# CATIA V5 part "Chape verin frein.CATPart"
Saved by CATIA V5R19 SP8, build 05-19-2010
Part number: Chape verin frein
Bounding box of the stored display mesh (mm): x -155 to 155, y -1185 to -885, z -1549.899 to -1325
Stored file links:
  G:\EU_thinkMotion\CFAO_2010\MMS_groupe3\MMS_groupe3\rdalborgo\rdalborgo\Chape verin frein.CATPart
  G:\EU_thinkMotion\CFAO_2010\MMS_groupe3\MMS_groupe3\rdalborgo\rdalborgo\rdalborgo.CATProduct
  G:\EU_thinkMotion\CFAO_2010\MMS_groupe3\MMS_groupe3\rdalborgo\rdalborgo\Support A.CATPart
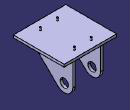
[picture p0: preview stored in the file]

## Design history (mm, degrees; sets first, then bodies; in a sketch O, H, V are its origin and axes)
External parameters (linked from other documents)
  `External.Largeur bielle` = 210 mm
Set1
  Plane1: linked copy from another document
  Point1: linked copy from another document
  Point2 "A verin frein": linked copy from another document
  Plane2: linked copy from another document
  Plane3: linked copy from another document
Body1 (main body)
  Sketch1 on Plane1, origin (0, -950, 0), H (-1, 0, 0), V (0, 0, 1)
    line L1 (155, -1340) -> (-155, -1340)
    line L2 (-155, -1340) -> (-155, -1355)
    line L3 (-155, -1355) -> (-90, -1355)
    line L4 (-90, -1355) -> (-90, -1550)
    line L5 (-90, -1550) -> (-75, -1550)
    line L6 (-75, -1550) -> (-75, -1355)
    point P7 (-75, -1355)
    line L7 (-75, -1355) -> (75, -1355)
    line L8 (75, -1355) -> (75, -1550)
    point P9 (75, -1550)
    line L9 (75, -1550) -> (90, -1550)
    line L10 (90, -1550) -> (90, -1355)
    point P11 (90, -1355)
    line L11 (90, -1355) -> (155, -1355)
    line L12 (155, -1355) -> (155, -1340)
    reference projected point E1 (0, -1340) from Point1
    reference projected point E2 (0, -1340) from Point1
    reference projected point E3 (0, -1340) from Point1
    reference projected point E4 (0, -1500) from Point2
    distance L1 L3 = 15
    distance L10 L8 = 15
    distance L4 L6 = 15
    distance L2 L12 = 310 {= `External.Largeur bielle` +100mm}
    distance L6 L8 = 150
    distance L12 E2 = 155 {= (`External.Largeur bielle` +100mm)/2}
    distance L6 E3 = 75
    distance L5 E4 = 50
    horizontal: L1 H, L3 H, L5 H, L7 H, L9 H, L11 H
    vertical: L2 V, L4 V, L6 V, L8 V, L10 V, L12 V
    coincidence: P7 L3, P9 L5, P11 L3, L1 E1
  Sketch2 on Plane2, origin (0, 0, 0), H (0, 1, 0), V (0, 0, 1)
    point P1 (-950, -1500)
    reference projected point E1 (-950, -1500) from Point2
    line L1 (-900, -1355) -> (-900, -1500)
    point P3 (-900, -1500)
    line L2 (-900, -1355) -> (-885, -1355)
    line L3 (-885, -1355) -> (-885, -1340)
    line L4 (-885, -1340) -> (-1185, -1340)
    line L5 (-1185, -1340) -> (-1185, -1355)
    point P7 (-1185, -1355)
    line L6 (-1185, -1355) -> (-1170, -1355)
    point P9 (-900, -1500)
    reference intersected line E2 through (0, -1340) direction (-1, 0) from Plane3
    line L7 (-1170, -1355) -> (-984.9364, -1535.7694)
    arc A1 centre (-950, -1500) radius 50 from (-984.9364, -1535.7694) to (-900, -1500) ccw
    distance L4 L2 = 15
    length L2 = 15
    length L6 = 15
    length L4 = 300
    radius A1 = 50
    length L7 = 258.7008
    length L1 = 145
    coincidence: P1 E1, P7 L2, P3 P9, L4 E2
    horizontal: L2 H, L4 H, L6 H
    vertical: L3 V, L5 V, L1 V
  SolidCombine1: FirstComponentProfile Sketch1, FirstComponentDirection Sketch1, SecondComponentProfile Sketch2, SecondComponentDirection Sketch2
  Sketch3 on face of SolidCombine1 from Sketch1.L4, origin (90, 0, 0), H (0, 1, 0), V (0, 0, 1)
    circle A1 centre (-950, -1500) radius 25
    point P1 (-950, -1500)
    reference projected point E1 (-950, -1500) from Point2
    radius A1 = 25
    coincidence: P1 E1
  Pocket1: profile Sketch3, direction (-1, 0, 0), through (limit type 3)
  Sketch4 on face of SolidCombine1, origin (123.199, -1080.2639, -1355), H (1, 0, 0), V (0, -1, 0)
    point P1 (-73.199, 49.7361)
    reference intersected line E1 through (-123.199, 0) direction (0, 1) from Plane2
    reference intersected line E2 through (0, -130.2639) direction (1, 0) from Plane1
    distance E1 P1 = 50
    distance P1 E2 = 180
  Hole1: placed by Sketch4, at (50, -1130, -1355) direction (0, 0, 1), diameter 10, through (limit type 3)
  RectPattern1: of Hole1, direction 1 instances 2, spacing 100, along face of SolidCombine1, direction 2 instances 2, spacing 200, along face of SolidCombine1
Body2 "Vis 1"
  Sketch5 on face of SolidCombine1, origin (-1475, 0, -1355), H (0, -1, 0), V (-1, 0, 0)
    circle A1 centre (1130, -1525) radius 5
    point P1 (1130, -1525)
    reference projected circle E1 centre (1130, -1525) radius 5 from edge [face of SolidCombine1 | face of Hole1]
    radius A1 = 5
    concentricity: P1 E1
  Pad1: profile Sketch5, direction (0, 0, 1), length 30
  Chamfer1: length 1, angle 45, on end face of Pad1
  Sketch6 on start face of Pad1, origin (-1475, 0, -1355), H (0, -1, 0), V (-1, 0, 0)
    circle A1 centre (1130, -1525) radius 7.5
    reference projected circle E1 centre (1130, -1525) radius 5 from edge [face of SolidCombine1 | face of Hole1]
    radius A1 = 7.5
    concentricity: A1 E1
  Pad2: profile Sketch6, direction (0, 0, -1), length 2
  Sketch7 on end face of Pad2, origin (-1479, 0, -1357), H (0, -1, 0), V (-1, 0, 0)
    point P1 (1130, -1529)
    point P2 (1126.8288, -1534.5024)
    point P3 (1133.1796, -1534.4976)
    point P4 (1136.3509, -1528.9952)
    point P5 (1133.1712, -1523.4976)
    point P6 (1126.8204, -1523.5024)
    point P7 (1123.6491, -1529.0048)
    point P8 (1130.0042, -1534.5)
    line L1 (1126.8288, -1534.5024) -> (1133.1796, -1534.4976)
    line L2 (1133.1796, -1534.4976) -> (1136.3509, -1528.9952)
    line L3 (1136.3509, -1528.9952) -> (1133.1712, -1523.4976)
    line L4 (1133.1712, -1523.4976) -> (1126.8204, -1523.5024)
    line L5 (1126.8204, -1523.5024) -> (1123.6491, -1529.0048)
    line L6 (1123.6491, -1529.0048) -> (1126.8288, -1534.5024)
    construction line L7 (1130, -1529) -> (1130.0042, -1534.5)
    construction circle A1 centre (1130, -1529) radius 6.3509
    construction arc A2 centre (1126.8204, -1523.5024) radius 6.3509 from (1133.1712, -1523.4976) to (1123.6491, -1529.0048) cw
    construction arc A3 centre (1133.1796, -1534.4976) radius 6.3509 from (1136.3509, -1528.9952) to (1126.8288, -1534.5024) ccw
    reference projected circle E1 centre (1130, -1529) radius 7.5 from edge [face of Pad2 from Sketch6.A1 | end face of Pad2]
    distance L4 P8 = 11
    coincidence: A1 P2, A1 P3, A1 P4, A1 P5, A1 P6, A1 P7, A2 P1, A3 P1
    midpoint: P8 L1
    parallelism: L1 L4
    concentricity: P1 E1
  Pad3: profile Sketch7, direction (0, 0, -1), length 5
Body3 "Vis2"
  Sketch8 on face of SolidCombine1, origin (-1475, 0, -1355), H (0, -1, 0), V (-1, 0, 0)
    circle A1 centre (1130, -1425) radius 5
    point P1 (1130, -1425)
    reference projected circle E1 centre (1130, -1425) radius 5 from edge [face of SolidCombine1 | face of RectPattern1]
    radius A1 = 5
    concentricity: P1 E1
  Pad4: profile Sketch8, direction (0, 0, 1), length 30
  Chamfer2: length 1, angle 45, on end face of Pad4
  Sketch9 on start face of Pad4, origin (-1475, 0, -1355), H (0, -1, 0), V (-1, 0, 0)
    circle A1 centre (1130, -1425) radius 7.5
    reference projected circle E1 centre (1130, -1425) radius 5 from edge [face of SolidCombine1 | face of RectPattern1]
    radius A1 = 7.5
    concentricity: A1 E1
  Pad5: profile Sketch9, direction (0, 0, -1), length 2
  Sketch10 on end face of Pad5, origin (-1479, 0, -1357), H (0, -1, 0), V (-1, 0, 0)
    point P1 (1130, -1429)
    point P2 (1126.8288, -1434.5024)
    point P3 (1133.1796, -1434.4976)
    point P4 (1136.3509, -1428.9952)
    point P5 (1133.1712, -1423.4976)
    point P6 (1126.8204, -1423.5024)
    point P7 (1123.6491, -1429.0048)
    point P8 (1130.0042, -1434.5)
    line L1 (1126.8288, -1434.5024) -> (1133.1796, -1434.4976)
    line L2 (1133.1796, -1434.4976) -> (1136.3509, -1428.9952)
    line L3 (1136.3509, -1428.9952) -> (1133.1712, -1423.4976)
    line L4 (1133.1712, -1423.4976) -> (1126.8204, -1423.5024)
    line L5 (1126.8204, -1423.5024) -> (1123.6491, -1429.0048)
    line L6 (1123.6491, -1429.0048) -> (1126.8288, -1434.5024)
    construction line L7 (1130, -1429) -> (1130.0042, -1434.5)
    construction circle A1 centre (1130, -1429) radius 6.3509
    construction arc A2 centre (1126.8204, -1423.5024) radius 6.3509 from (1133.1712, -1423.4976) to (1123.6491, -1429.0048) cw
    construction arc A3 centre (1133.1796, -1434.4976) radius 6.3509 from (1136.3509, -1428.9952) to (1126.8288, -1434.5024) ccw
    reference projected circle E1 centre (1130, -1429) radius 7.5 from edge [face of Pad5 from Sketch9.A1 | end face of Pad5]
    distance L4 P8 = 11
    coincidence: A1 P2, A1 P3, A1 P4, A1 P5, A1 P6, A1 P7, A2 P1, A3 P1
    midpoint: P8 L1
    parallelism: L1 L4
    concentricity: P1 E1
  Pad6: profile Sketch10, direction (0, 0, -1), length 5
Body4 "Vis 3"
  Sketch11 on face of SolidCombine1, origin (-1475, 0, -1355), H (0, -1, 0), V (-1, 0, 0)
    circle A1 centre (930, -1525) radius 5
    point P1 (930, -1525)
    reference projected circle E1 centre (930, -1525) radius 5 from edge [face of SolidCombine1 | face of RectPattern1]
    radius A1 = 5
    concentricity: P1 E1
  Pad7: profile Sketch11, direction (0, 0, 1), length 30
  Chamfer3: length 1, angle 45, on end face of Pad7
  Sketch12 on start face of Pad7, origin (-1475, 0, -1355), H (0, -1, 0), V (-1, 0, 0)
    circle A1 centre (930, -1525) radius 7.5
    reference projected circle E1 centre (930, -1525) radius 5 from edge [face of SolidCombine1 | face of RectPattern1]
    radius A1 = 7.5
    concentricity: A1 E1
  Pad8: profile Sketch12, direction (0, 0, -1), length 2
  Sketch13 on end face of Pad8, origin (-1479, 0, -1357), H (0, -1, 0), V (-1, 0, 0)
    point P1 (930, -1529)
    point P2 (926.8288, -1534.5024)
    point P3 (933.1796, -1534.4976)
    point P4 (936.3509, -1528.9952)
    point P5 (933.1712, -1523.4976)
    point P6 (926.8204, -1523.5024)
    point P7 (923.6491, -1529.0048)
    point P8 (930.0042, -1534.5)
    line L1 (926.8288, -1534.5024) -> (933.1796, -1534.4976)
    line L2 (933.1796, -1534.4976) -> (936.3509, -1528.9952)
    line L3 (936.3509, -1528.9952) -> (933.1712, -1523.4976)
    line L4 (933.1712, -1523.4976) -> (926.8204, -1523.5024)
    line L5 (926.8204, -1523.5024) -> (923.6491, -1529.0048)
    line L6 (923.6491, -1529.0048) -> (926.8288, -1534.5024)
    construction line L7 (930, -1529) -> (930.0042, -1534.5)
    construction circle A1 centre (930, -1529) radius 6.3509
    construction arc A2 centre (926.8204, -1523.5024) radius 6.3509 from (933.1712, -1523.4976) to (923.6491, -1529.0048) cw
    construction arc A3 centre (933.1796, -1534.4976) radius 6.3509 from (936.3509, -1528.9952) to (926.8288, -1534.5024) ccw
    reference projected circle E1 centre (930, -1529) radius 7.5 from edge [face of Pad8 from Sketch12.A1 | end face of Pad8]
    distance L4 P8 = 11
    coincidence: A1 P2, A1 P3, A1 P4, A1 P5, A1 P6, A1 P7, A2 P1, A3 P1
    midpoint: P8 L1
    parallelism: L1 L4
    concentricity: P1 E1
  Pad9: profile Sketch13, direction (0, 0, -1), length 5
Body5 "Vis 4"
  Sketch14 on face of SolidCombine1, origin (-1475, 0, -1355), H (0, -1, 0), V (-1, 0, 0)
    circle A1 centre (930, -1425) radius 5
    point P1 (930, -1425)
    reference projected circle E1 centre (930, -1425) radius 5 from edge [face of SolidCombine1 | face of RectPattern1]
    radius A1 = 5
    concentricity: P1 E1
  Pad10: profile Sketch14, direction (0, 0, 1), length 30
  Chamfer4: length 1, angle 45, on end face of Pad10
  Sketch15 on start face of Pad10, origin (-1475, 0, -1355), H (0, -1, 0), V (-1, 0, 0)
    circle A1 centre (930, -1425) radius 7.5
    reference projected circle E1 centre (930, -1425) radius 5 from edge [face of SolidCombine1 | face of RectPattern1]
    radius A1 = 7.5
    concentricity: A1 E1
  Pad11: profile Sketch15, direction (0, 0, -1), length 2
  Sketch16 on end face of Pad11, origin (-1479, 0, -1357), H (0, -1, 0), V (-1, 0, 0)
    point P1 (930, -1429)
    point P2 (926.8288, -1434.5024)
    point P3 (933.1796, -1434.4976)
    point P4 (936.3509, -1428.9952)
    point P5 (933.1712, -1423.4976)
    point P6 (926.8204, -1423.5024)
    point P7 (923.6491, -1429.0048)
    point P8 (930.0042, -1434.5)
    line L1 (926.8288, -1434.5024) -> (933.1796, -1434.4976)
    line L2 (933.1796, -1434.4976) -> (936.3509, -1428.9952)
    line L3 (936.3509, -1428.9952) -> (933.1712, -1423.4976)
    line L4 (933.1712, -1423.4976) -> (926.8204, -1423.5024)
    line L5 (926.8204, -1423.5024) -> (923.6491, -1429.0048)
    line L6 (923.6491, -1429.0048) -> (926.8288, -1434.5024)
    construction line L7 (930, -1429) -> (930.0042, -1434.5)
    construction circle A1 centre (930, -1429) radius 6.3509
    construction arc A2 centre (926.8204, -1423.5024) radius 6.3509 from (933.1712, -1423.4976) to (923.6491, -1429.0048) cw
    construction arc A3 centre (933.1796, -1434.4976) radius 6.3509 from (936.3509, -1428.9952) to (926.8288, -1434.5024) ccw
    reference projected circle E1 centre (930, -1429) radius 7.5 from edge [face of Pad11 from Sketch15.A1 | end face of Pad11]
    distance L4 P8 = 11
    coincidence: A1 P2, A1 P3, A1 P4, A1 P5, A1 P6, A1 P7, A2 P1, A3 P1
    midpoint: P8 L1
    parallelism: L1 L4
    concentricity: P1 E1
  Pad12: profile Sketch16, direction (0, 0, -1), length 5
